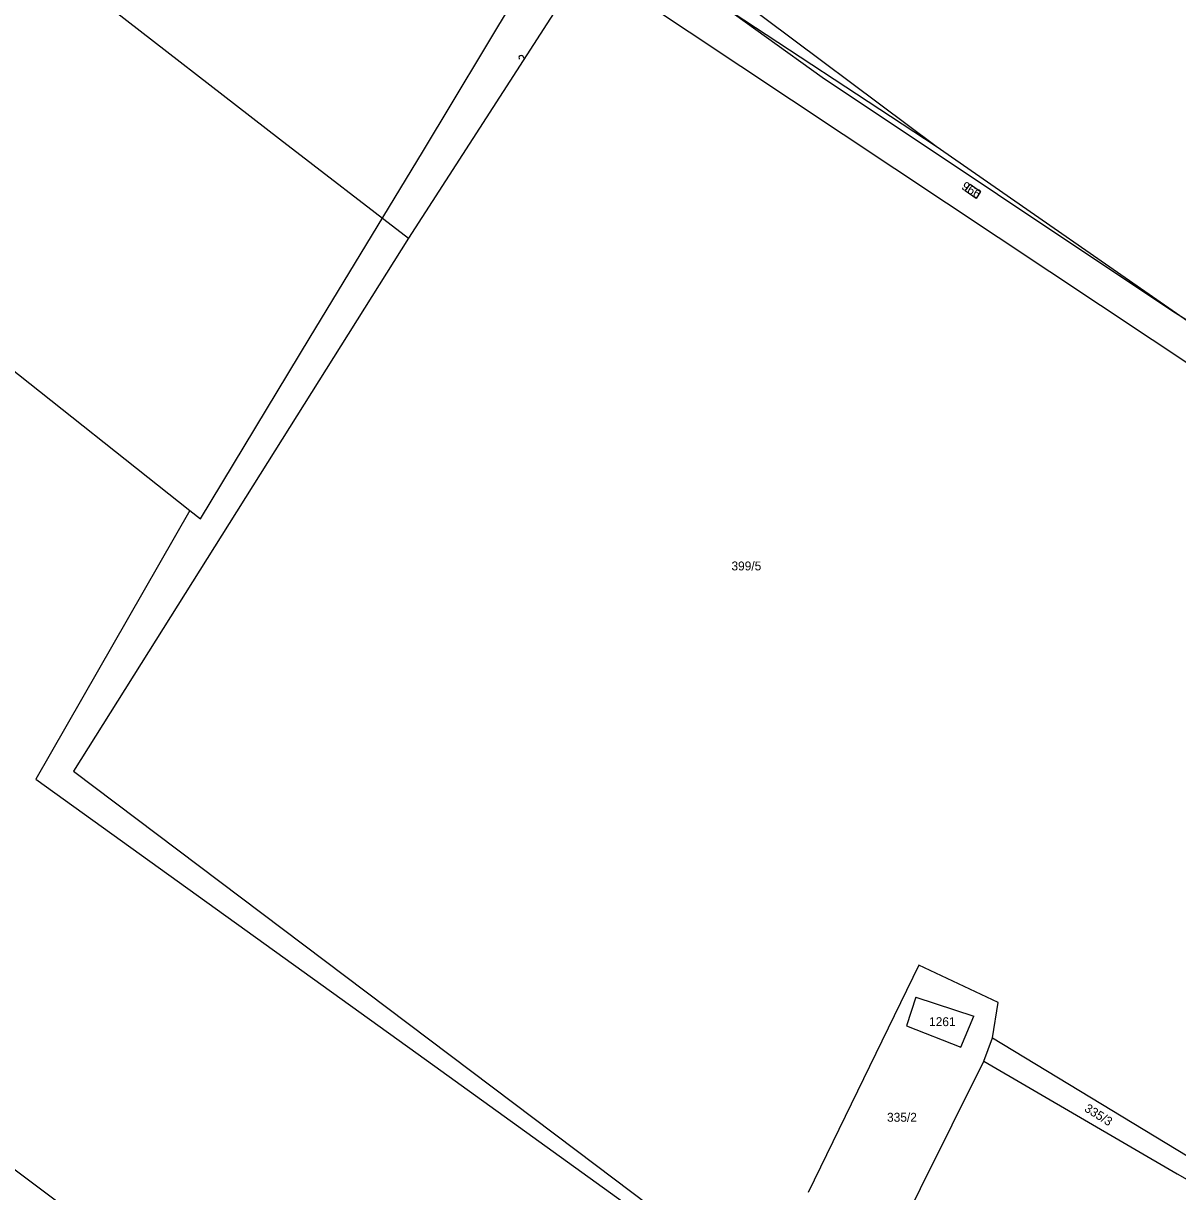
# Model space of a CAD drawing. Extents: x -581999 to -572728, y -1219553 to -1212032.
# Drawn here: x -577046.4 to -576787.2, y -1214668.1 to -1214405.7 of the extents above; entities that cross this region are included whole.
import ezdxf

# ---------------------------------------------------------------- set-up
doc = ezdxf.new("R2010")
doc.units = 0
for name, color, linetype in [('Vrstva 1', 7, 'Continuous'), ('Vrstva 2', 7, 'Continuous'), ('Vrstva 6', 7, 'Continuous'), ('Vrstva 60', 7, 'Continuous'), ('Vrstva 61', 7, 'Continuous')]:
    doc.layers.add(name, color=color, linetype=linetype)

msp = doc.modelspace()

# ---------------------------------------------------------------- linework, layer by layer
at = {"layer": 'Vrstva 1'}
for p, q in [((-577105.66, -1214341.074), (-576988.865, -1214431.642)), ((-576948.611, -1214353.222), (-576841.433, -1214433.289)), ((-576915.268, -1214384.747), (-576959.96, -1214453.948)), ((-576915.268, -1214384.747), (-576841.433, -1214433.289)), ((-576988.865, -1214431.642), (-576959.96, -1214453.948)), ((-576841.433, -1214433.289), (-576768.78, -1214483.891)), ((-576959.96, -1214453.948), (-577035.155, -1214573.719)), ((-577035.155, -1214573.719), (-576917.751, -1214662.217))]:
    msp.add_line(p, q, dxfattribs=at)
for points in [[(-576833.818, -1214441.855), (-576831.49, -1214443.522), (-576832.488, -1214445.028), (-576834.927, -1214443.307)], [(-576834.927, -1214443.307), (-576833.818, -1214441.855)], [(-576930.254, -1214757.061), (-576935.99, -1214747.903), (-576959.905, -1214728.809), (-576982.36, -1214712.757), (-577058.553, -1214655.612), (-577135.842, -1214594.867), (-577143.306, -1214589.054)], [(-576845.351, -1214617.227), (-576870.202, -1214668.333)], [(-576827.523, -1214625.614), (-576845.351, -1214617.227)], [(-576846.03, -1214624.412), (-576848.128, -1214630.901), (-576835.897, -1214635.69), (-576833.027, -1214628.687)], [(-576846.03, -1214624.412), (-576833.027, -1214628.687)], [(-576828.803, -1214633.616), (-576827.523, -1214625.614)], [(-576830.776, -1214638.839), (-576828.803, -1214633.616)], [(-576828.803, -1214633.616), (-576775.229, -1214666.079)], [(-576852.104, -1214681.699), (-576830.776, -1214638.839)], [(-576830.776, -1214638.839), (-576787.336, -1214664.153)], [(-576917.751, -1214662.217), (-576858.851, -1214706.697), (-576856.723, -1214708.693), (-576795.006, -1214754.605)], [(-576787.336, -1214664.153), (-576782.858, -1214666.644), (-576775.193, -1214670.803)]]:
    msp.add_lwpolyline(points, dxfattribs=at)
at = {"layer": 'Vrstva 6'}
msp.add_open_spline([(-576933.959, -1214413.652), (-576934.262, -1214412.853), (-576935.009, -1214412.994), (-576935.175, -1214413.36), (-576935.08, -1214413.616), (-576935.055, -1214413.733)], degree=3, dxfattribs=at)
at = {"layer": 'Vrstva 60'}
for p, q in [((-576867.04, -1214417.92), (-576924.26, -1214376.6)), ((-576956.787, -1214434.632), (-576928.05, -1214386.89)), ((-576928.05, -1214386.89), (-576779.92, -1214485.4)), ((-576788.34, -1214470.46), (-576867.04, -1214417.92)), ((-577112.865, -1214432.766), (-577009.019, -1214515.15)), ((-576981.979, -1214476.228), (-576956.787, -1214434.632)), ((-576726.85, -1214508.69), (-576788.34, -1214470.46)), ((-577006.65, -1214517.03), (-576981.979, -1214476.228)), ((-577009.019, -1214515.15), (-577006.65, -1214517.03))]:
    msp.add_line(p, q, dxfattribs=at)
at = {"layer": 'Vrstva 61'}
for p, q in [((-577009.019, -1214515.15), (-577043.573, -1214575.498)), ((-577043.573, -1214575.498), (-576955.878, -1214638.589)), ((-576955.878, -1214638.589), (-576795.006, -1214754.605))]:
    msp.add_line(p, q, dxfattribs=at)

# ---------------------------------------------------------------- texts
at = {"layer": 'Vrstva 2'}
for s, p in [('966', (-576835.94, -1214442.81)), ('335/3', (-576808.347, -1214649.938))]:
    msp.add_text(s, height=2, rotation=327.95838, dxfattribs=at).set_placement(p)
for s, p in [('399/5', (-576887.412, -1214528.595)), ('1261', (-576843.042, -1214630.952)), ('335/2', (-576852.476, -1214652.425))]:
    msp.add_text(s, height=2, dxfattribs=at).set_placement(p)

doc.saveas('drawing.dxf')
